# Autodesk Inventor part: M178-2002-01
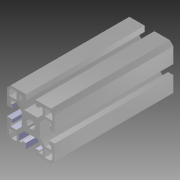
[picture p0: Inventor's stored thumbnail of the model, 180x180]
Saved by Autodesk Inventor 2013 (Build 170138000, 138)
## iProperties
Created: 2004-10
Material: Aluminium - 6061
Document SubType Name: Modeling
Designer: Autodesk, Inc.
Manufacturer: Standard
Standards Organization: Custom
Description: PC RACK, UPRIGHT, LEFT
Stock Number: 10-540
Catalog Web Link: http://www.parker.com/ead/cm1.asp?cmid=809
Vendor: PARKER IPS
Part Number: M178-2002-01
Mass: 179.948 g
Surface Area: 483.565 cm^2
Volume: 66.4013 cm^3
Density: 2.71 g/cm^3
CAGE: 1LJX3
Dept. ID: Product Design
Description #2: ---
Finish #1: ---
Finish #2: ---
Material ID: ---
Project Number: ---
Stock Number: 10-040
Length: 184.150 mm
Author: Autodesk, Inc.
Revision Number: A
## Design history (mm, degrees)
derived "40 Series Profiles.ipt"
feature "IPS40SeriesCutout1"
feature "IPS40SeriesCutout2"
body "Solid1"
tag "TaggingFeature2"
sketch "Sketch1"
  geometry: L1 (20, 64.3)-(7, -119.85) reference; L2 (7, 64.3)-(7, -119.85) reference; L3 (-1, -119.85)-(-1, 64.3) reference; L4 (7, 44.3)-(-1, 44.3); C1 r 10 at (3, 44.3)
  constraints: 2 end point, 2 point on line, 1 centre point, 1 midpoint, 1 perpendicular
  dimensions: "d0" = 20 distance between parallel lines of L4 L1; "d1" = 20 diameter of C1
sketch "Sketch2"
  geometry: L1 (-56.35, -43.5)-(-56.35, -43.5) reference; L2 (127.8, -43.5)-(-56.35, -43.5) reference; L3 (-56.35, -35.5)-(127.8, -35.5) reference; L4 (-36.35, -43.5)-(-36.35, -35.5); C1 r 10 at (-36.35, -39.5)
  constraints: 2 end point, 2 point on line, 1 centre point, 1 midpoint, 1 perpendicular
  dimensions: "d2" = 20 distance between parallel lines of L4 L1; "d3" = 20 diameter of C1
feature "Solid1::40 Series Profiles.ipt" dims "ScaleForDerivedMember" = 10
other parameters: "Length" = 184.15
